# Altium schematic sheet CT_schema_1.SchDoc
size 380 x 258 mm
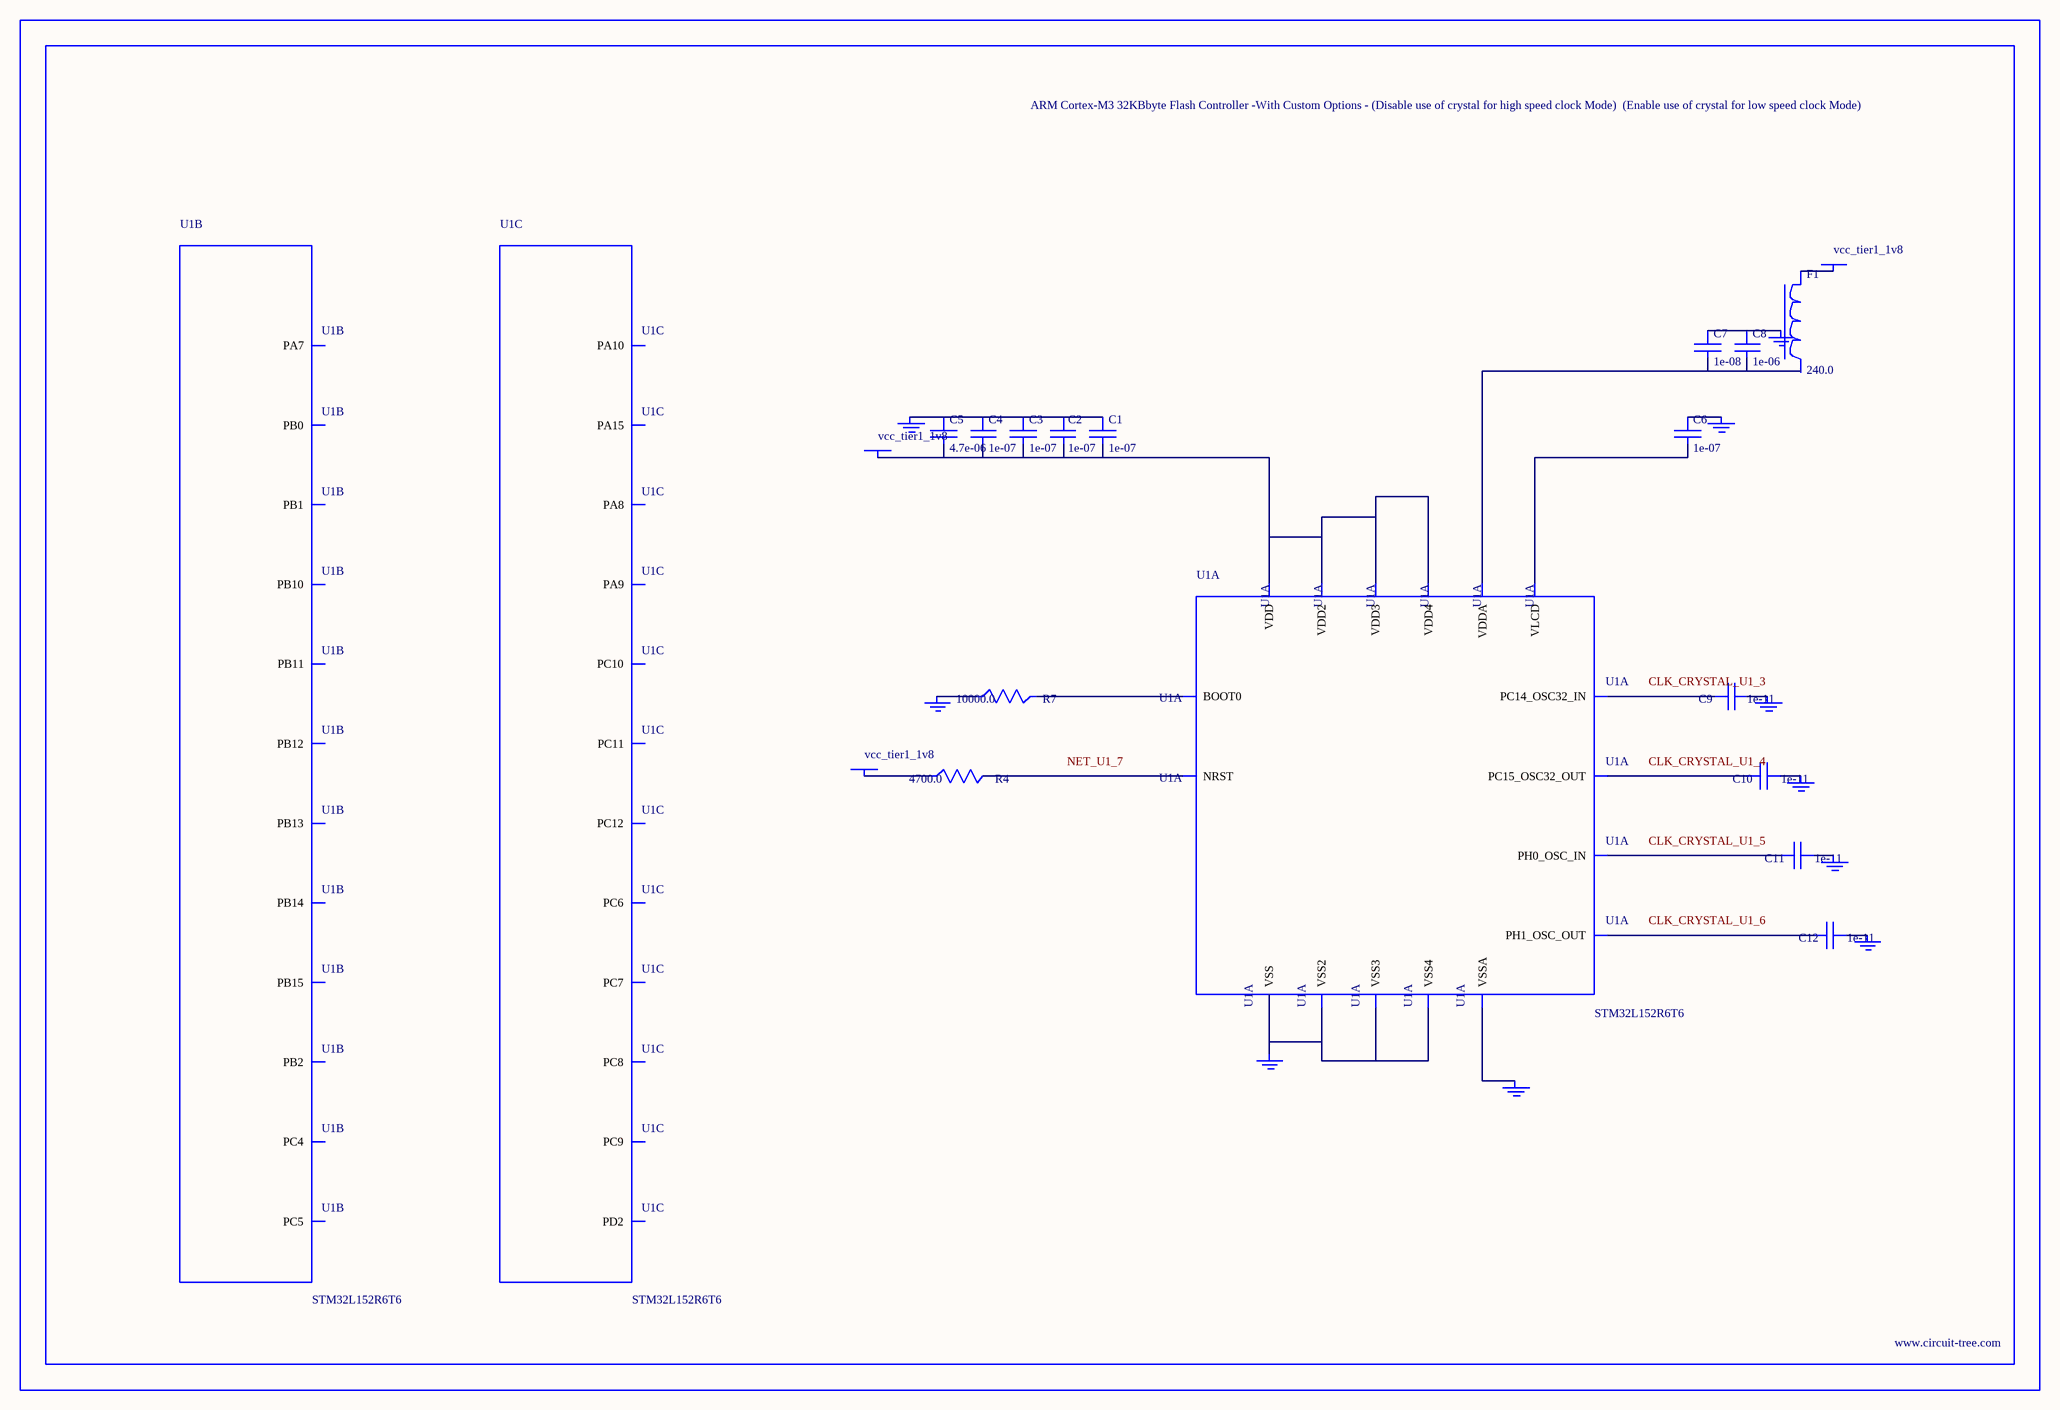
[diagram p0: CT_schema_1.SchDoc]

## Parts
BORDER0  (no value)
C1  1e-07  [C0603]
C2  1e-07  [C0603]
C3  1e-07  [C0603]
C4  1e-07  [C0603]
C5  4.7e-06  [C0603]
C6  1e-07  [C0603]
C7  1e-08  [C0603]
C8  1e-06  [C0603]
C9  1e-11  [C0402]
C10  1e-11  [C0402]
C11  1e-11  [C0402]
C12  1e-11  [C0402]
F1  240.0  [L0603]
GND_INSTANCE_0_0  (no value)
GND_INSTANCE_0_1  (no value)
GND_INSTANCE_0_2  (no value)
GND_INSTANCE_0_3  (no value)
GND_INSTANCE_0_4  (no value)
GND_INSTANCE_0_5  (no value)
GND_INSTANCE_0_6  (no value)
GND_INSTANCE_0_7  (no value)
GND_INSTANCE_0_8  (no value)
GND_INSTANCE_0_9  (no value)
POWER_INSTANCE_0_0  vcc_tier1_1v8
POWER_INSTANCE_0_1  vcc_tier1_1v8
POWER_INSTANCE_0_2  vcc_tier1_1v8
R4  4700.0  [R0603]
R7  10000.0  [R0603]
U1  STM32L152R6T6  [LQFP64]  (parts A,B,C of 7)

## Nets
NetC1_1: C1.1 C2.1 C3.1 C4.1 C5.1 GND_INSTANCE_0_7.0(GND)
NetC1_2: C1.2 C2.2 C3.2 C4.2 C5.2 POWER_INSTANCE_0_1.0(PWR) U1.19(VDD) U1.32(VDD2) U1.48(VDD3) U1.64(VDD4)
NetC6_1: C6.1 GND_INSTANCE_0_0.0(GND)
NetC6_2: C6.2 U1.1(VLCD)
NetC7_1: C7.1 C8.1 GND_INSTANCE_0_6.0(GND)
NetC7_2: C7.2 C8.2 U1.13(VDDA)
NetC9_1: C9.1 GND_INSTANCE_0_1.0(GND)
NetC9_2: C9.2 U1.3(PC14_OSC32_IN)
NetC10_1: C10.1 GND_INSTANCE_0_2.0(GND)
NetC10_2: C10.2 U1.4(PC15_OSC32_OUT)
NetC11_1: C11.1 GND_INSTANCE_0_3.0(GND)
NetC11_2: C11.2 U1.5(PH0_OSC_IN)
NetC12_1: C12.1 GND_INSTANCE_0_4.0(GND)
NetC12_2: C12.2 U1.6(PH1_OSC_OUT)
NetF1_1: F1.1 POWER_INSTANCE_0_0.0(PWR)
NetGND_INSTANCE_0_5_0: GND_INSTANCE_0_5.0(GND) U1.12(VSSA)
NetGND_INSTANCE_0_8_0: GND_INSTANCE_0_8.0(GND) R7.1
NetGND_INSTANCE_0_9_0: GND_INSTANCE_0_9.0(GND) U1.18(VSS) U1.31(VSS2) U1.47(VSS3) U1.63(VSS4)
NetPOWER_INSTANCE_0_2_0: POWER_INSTANCE_0_2.0(PWR) R4.1
NetR4_2: R4.2 U1.7(NRST)
NetR7_2: R7.2 U1.60(BOOT0)

Not connected (* = marked no-connect by the designer): F1 2; U1 23(PA7) 24(PC4) 25(PC5) 26(PB0) 27(PB1) 28(PB2) 29(PB10) 30(PB11) 33(PB12) 34(PB13) 35(PB14) 36(PB15) 37(PC6) 38(PC7) 39(PC8) 40(PC9) 41(PA8) 42(PA9) 43(PA10) 50(PA15) 51(PC10) 52(PC11) 53(PC12) 54(PD2)

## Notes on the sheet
- Labels drawn without touching a wire or pin: CLK_CRYSTAL_U1_3, CLK_CRYSTAL_U1_4, CLK_CRYSTAL_U1_5, CLK_CRYSTAL_U1_6, NET_U1_7

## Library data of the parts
BORDER0 = BORDER_PAGE0
C1-C4 C6 = 06035C104K4Z2A
C5 = GRM188R6YA475KE15D
C7 = 06035C103K4Z2A
C8 = C0603C105K3RACTU
C9-C12 = C0402C100K3GACTU
F1 = Z0603C241ASMST
GND_INSTANCE_0_0-GND_INSTANCE_0_9 = GND
POWER_INSTANCE_0_0-POWER_INSTANCE_0_2 = PWR
R4 = RC0603JR-074K7L
R7 = RC0603JR-0710KL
